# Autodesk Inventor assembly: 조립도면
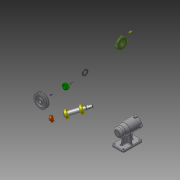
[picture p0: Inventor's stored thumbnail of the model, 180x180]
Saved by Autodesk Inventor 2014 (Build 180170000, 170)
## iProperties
Created: 2019-07
Part Number: 조립도면
Document SubType Name: Assembly
Designer: kh
Author: kh
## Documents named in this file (12)
- C:\Users\kh\Desktop\490704V1076\조립도면.iam
- C:\Users\kh\Desktop\490704V1076\본체.ipt
- C:\Users\kh\Desktop\490704V1076\V벨트풀리.ipt
- C:\Users\kh\Desktop\490704V1076\멈춤나사 M3.ipt
- C:\Users\kh\Desktop\490704V1076\베어링 6004.ipt
- C:\Users\kh\Desktop\490704V1076\베어링 51202.ipt
- C:\Users\kh\Desktop\490704V1076\볼트 M4.ipt
- C:\Users\kh\Desktop\490704V1076\어댑터슬리브.ipt
- C:\Users\kh\Desktop\490704V1076\오일 실.ipt
- C:\Users\kh\Desktop\490704V1076\축.ipt
- C:\Users\kh\Desktop\490704V1076\커버.ipt
- C:\Users\kh\Desktop\490704V1076\키 5 x 5 x 16.ipt
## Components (1 placed, 1 different names)
1. V벨트풀리:1
